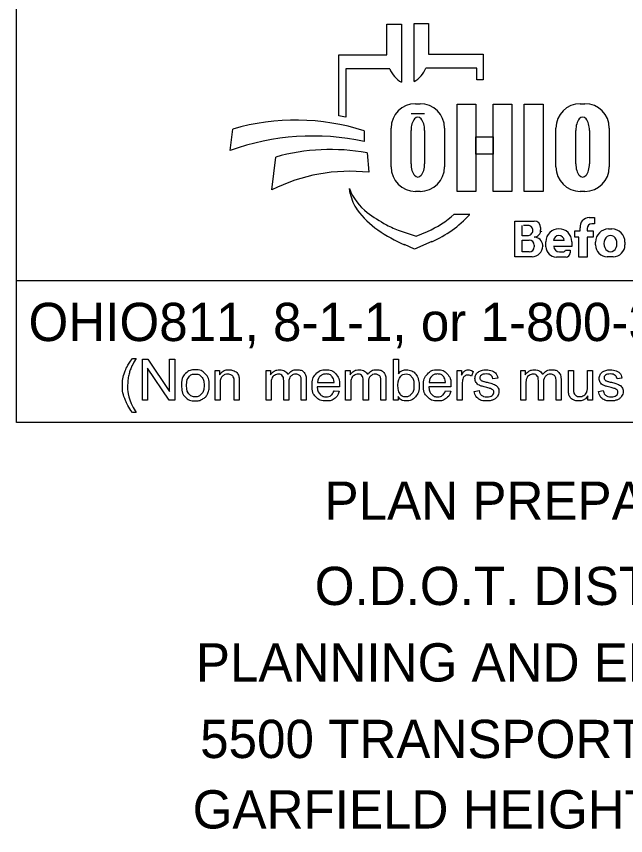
# Model space of a CAD drawing. Extents: x -17.5 to 72.9, y -57.8 to 32.3.
# Drawn here: x 41.886 to 44.116, y -57.698 to -54.7 of the extents above; entities that cross this region are included whole.
import ezdxf

# ---------------------------------------------------------------- set-up
doc = ezdxf.new("R2010")
doc.units = 0
doc.layers.add('SH_Data', color=7, linetype='Continuous')
doc.layers.add('SH_Text', color=7, linetype='Continuous')

msp = doc.modelspace()

# ---------------------------------------------------------------- linework, layer by layer
at = {"layer": 'SH_Data'}
for p, q in [((41.8861, -56.1862), (41.8861, -53.8487)), ((46.1361, -55.6683), (41.8861, -55.6683)), ((46.1361, -56.1862), (41.8861, -56.1862))]:
    msp.add_line(p, q, dxfattribs=at)
at = {"layer": 'SH_Text'}
for p, q in [((43.2421, -54.8407), (43.2421, -54.7292)), ((43.2421, -54.7292), (43.2957, -54.7292)), ((43.2957, -54.7292), (43.2957, -54.9412)), ((43.3414, -54.9389), (43.3414, -54.7268)), ((43.3414, -54.7268), (43.395, -54.7268)), ((43.395, -54.7268), (43.395, -54.8383)), ((43.0661, -55.0646), (43.0661, -54.8407)), ((43.0661, -54.8407), (43.2421, -54.8407)), ((43.395, -54.8383), (43.5943, -54.8383)), ((43.5943, -54.8383), (43.5943, -54.9322)), ((43.571, -54.8898), (43.3846, -54.8898)), ((43.571, -54.9322), (43.571, -54.8898)), ((43.0914, -54.8921), (43.0914, -55.069)), ((43.2525, -54.8921), (43.0914, -54.8921)), ((43.5943, -54.9322), (43.571, -54.9322)), ((43.3471, -55.0198), (43.3636, -55.0198)), ((43.9501, -55.0198), (43.9667, -55.0198)), ((43.3804, -55.0569), (43.3306, -55.0569)), ((42.6688, -55.1909), (42.6782, -55.1127)), ((43.1594, -55.1192), (43.1594, -55.158)), ((43.2576, -55.2513), (43.2576, -55.1093)), ((43.3305, -55.2399), (43.3305, -55.1176)), ((43.3803, -55.1176), (43.3803, -55.2399)), ((43.4531, -55.1093), (43.4531, -55.2513)), ((43.8607, -55.2513), (43.8607, -55.1093)), ((43.9336, -55.2399), (43.9336, -55.1176)), ((43.9834, -55.1176), (43.9834, -55.2399)), ((44.0561, -55.1093), (44.0561, -55.2513)), ((42.8206, -55.3354), (42.8353, -55.2153)), ((43.1694, -55.1998), (43.1756, -55.2708)), ((43.1083, -55.3483), (43.1052, -55.3304)), ((43.3636, -55.3408), (43.3471, -55.3408)), ((43.9667, -55.3408), (43.9501, -55.3408)), ((43.4886, -55.4242), (43.546, -55.4242)), ((43.7099, -55.5799), (43.7099, -55.4492)), ((43.7099, -55.4492), (43.7811, -55.4492)), ((43.9825, -55.4364), (44.0019, -55.4364)), ((44.0019, -55.4599), (43.9918, -55.4599)), ((44.0019, -55.4364), (44.0019, -55.4594)), ((43.2902, -55.4845), (43.3496, -55.505)), ((43.3496, -55.505), (43.3906, -55.4872)), ((43.7378, -55.5027), (43.7378, -55.4657)), ((43.763, -55.4657), (43.7418, -55.4657)), ((43.8048, -55.473), (43.8048, -55.4809)), ((43.9299, -55.5078), (43.9299, -55.4848)), ((43.9299, -55.4848), (43.9492, -55.4848)), ((43.9492, -55.4848), (43.9492, -55.4743)), ((43.9753, -55.4763), (43.9753, -55.4848)), ((43.9753, -55.4848), (43.9968, -55.4848)), ((43.9968, -55.4848), (43.9968, -55.5078)), ((44.0537, -55.4782), (44.0658, -55.4782)), ((43.7573, -55.5027), (43.7378, -55.5027)), ((43.7378, -55.5621), (43.7378, -55.5192)), ((43.7378, -55.5192), (43.7634, -55.5192)), ((43.891, -55.5207), (43.8525, -55.5207)), ((43.9448, -55.5078), (43.9299, -55.5078)), ((43.9448, -55.5811), (43.9448, -55.5078)), ((43.9968, -55.5078), (43.9753, -55.5078)), ((43.9753, -55.5078), (43.9753, -55.5811)), ((43.3436, -55.552), (43.3062, -55.5356)), ((43.4068, -55.5246), (43.3436, -55.552)), ((43.7815, -55.5373), (43.7815, -55.5437)), ((43.8129, -55.5402), (43.8129, -55.5406)), ((43.8244, -55.5431), (43.8244, -55.5247)), ((43.919, -55.5424), (43.8525, -55.5424)), ((43.919, -55.5247), (43.919, -55.5424)), ((44.0059, -55.5368), (44.0059, -55.526)), ((44.1136, -55.526), (44.1136, -55.5368)), ((43.7735, -55.5799), (43.7099, -55.5799)), ((43.7631, -55.5621), (43.7378, -55.5621)), ((43.8735, -55.5616), (43.8876, -55.5616)), ((43.8962, -55.5561), (43.913, -55.5561)), ((43.913, -55.5561), (43.913, -55.5659)), ((44.0708, -55.5796), (44.0486, -55.5796)), ((43.8978, -55.5811), (43.8624, -55.5811)), ((43.9753, -55.5811), (43.9448, -55.5811))]:
    msp.add_line(p, q, dxfattribs=at)
for points in [[(43.4995, -55.0209), (43.5675, -55.0209), (43.5675, -55.3409), (43.4995, -55.3409)], [(43.6317, -55.0209), (43.6996, -55.0209), (43.6996, -55.3409), (43.6317, -55.3409)], [(43.745, -55.0209), (43.8138, -55.0209), (43.8138, -55.3409), (43.745, -55.3409)], [(43.5675, -55.1408), (43.6317, -55.1408), (43.6317, -55.2048), (43.5675, -55.2048)]]:
    msp.add_lwpolyline(points, close=True, dxfattribs=at)
for points in [[(42.3107, -55.9524), (42.3239, -55.9524)], [(42.3474, -56.105), (42.3474, -55.9549), (42.3678, -55.9549), (42.4468, -56.0728), (42.4468, -55.9549), (42.4658, -55.9549), (42.4658, -56.105), (42.4454, -56.105), (42.3664, -55.9871), (42.3664, -56.105), (42.3474, -56.105)], [(43.2829, -56.105), (43.2658, -56.105), (43.2658, -55.9549), (43.2843, -55.9549), (43.2843, -56.0084)], [(42.6134, -56.105), (42.6134, -55.9962), (42.63, -55.9962), (42.63, -56.0117)], [(42.7998, -56.105), (42.7998, -55.9962), (42.8163, -55.9962), (42.8163, -56.0116)], [(43.0912, -56.105), (43.0912, -55.9962), (43.1077, -55.9962), (43.1077, -56.0116)], [(43.499, -56.105), (43.499, -55.9962), (43.5156, -55.9962), (43.5156, -56.0127)], [(43.558, -55.9997), (43.5516, -56.0167)], [(43.7322, -56.105), (43.7322, -55.9962), (43.7487, -55.9962), (43.7487, -56.0116)], [(43.9065, -56.0636), (43.9065, -55.9962), (43.9249, -55.9962), (43.9249, -56.0565)], [(43.9762, -56.0545), (43.9762, -55.9962), (43.9946, -55.9962), (43.9946, -56.105), (43.9781, -56.105)], [(42.9473, -56.0304), (42.9473, -56.105), (42.9289, -56.105), (42.9289, -56.0365)], [(43.2387, -56.0304), (43.2387, -56.105), (43.2203, -56.105), (43.2203, -56.0365)], [(43.648, -56.0244), (43.6299, -56.0268)], [(43.8797, -56.0304), (43.8797, -56.105), (43.8613, -56.105), (43.8613, -56.0365)], [(44.1025, -56.0244), (44.0845, -56.0268)], [(42.6318, -56.0457), (42.6318, -56.105), (42.6134, -56.105)], [(42.7017, -56.0382), (42.7017, -56.105), (42.6833, -56.105), (42.6833, -56.0389)], [(42.8182, -56.0486), (42.8182, -56.105), (42.7998, -56.105)], [(42.8829, -56.0419), (42.8829, -56.105), (42.8645, -56.105), (42.8645, -56.0344)], [(43.0685, -56.0554), (42.9874, -56.0554)], [(42.9884, -56.0403), (43.0492, -56.0403)], [(43.1096, -56.0486), (43.1096, -56.105), (43.0912, -56.105)], [(43.1743, -56.0419), (43.1743, -56.105), (43.1558, -56.105), (43.1558, -56.0344)], [(43.4765, -56.0554), (43.3954, -56.0554)], [(43.3964, -56.0403), (43.4572, -56.0403)], [(43.5174, -56.0481), (43.5174, -56.105), (43.499, -56.105)], [(43.7506, -56.0486), (43.7506, -56.105), (43.7322, -56.105)], [(43.8153, -56.0419), (43.8153, -56.105), (43.7968, -56.105), (43.7968, -56.0344)], [(43.049, -56.0699), (43.068, -56.0723)], [(43.457, -56.0699), (43.476, -56.0723)], [(43.5616, -56.0725), (43.5798, -56.0697)], [(43.9781, -56.105), (43.9781, -56.089)], [(44.0161, -56.0725), (44.0343, -56.0697)], [(43.2829, -56.0914), (43.2829, -56.105)], [(42.3239, -56.1492), (42.3107, -56.1492)]]:
    msp.add_lwpolyline(points, dxfattribs=at)
for centre, radius, start, end in [((43.2933, -54.853), 0.0985, 299.2531, 338.0704), ((43.3438, -54.8553), 0.0985, 201.9296, 240.7469), ((43.3471, -55.1093), 0.0895, 90, 180), ((43.3636, -55.1093), 0.0895, 0, 90), ((43.9501, -55.1093), 0.0895, 90, 180), ((43.9667, -55.1093), 0.0895, 0, 90), ((42.938, -55.8735), 0.8191, 79.2074, 81.0007), ((42.9082, -55.8988), 0.8191, 72.1402, 106.3144), ((42.9713, -56.0299), 0.8919, 77.8238, 109.8274), ((43.0352, -55.9196), 0.7322, 79.44, 105.8467), ((43.1073, -55.9028), 0.6357, 83.8248, 116.8021), ((43.3471, -55.2513), 0.0895, 180, 270), ((43.3636, -55.2513), 0.0895, 270, 0), ((43.9501, -55.2513), 0.0895, 180, 270), ((43.9667, -55.2513), 0.0895, 270, 0), ((43.2926, -55.2583), 0.2008, 201.0457, 232.5314), ((43.2496, -55.3242), 0.1433, 189.6817, 216.0884), ((43.3833, -55.2267), 0.3088, 216.0884, 235.7167), ((43.4852, -55.007), 0.5173, 232.5314, 241.794), ((43.2472, -55.1568), 0.3602, 293.4582, 312.0712), ((43.2472, -55.1568), 0.401, 293.4582, 317.8286), ((43.7811, -55.473), 0.0238, 0, 90), ((43.9825, -55.4699), 0.0335, 90, 187.5187), ((43.9918, -55.4763), 0.0165, 90, 180), ((43.5498, -54.9825), 0.6044, 235.7167, 246.2325), ((43.4, -55.1659), 0.3371, 241.794, 250.9821), ((43.7573, -55.4839), 0.0187, 270, 2.0582), ((43.7591, -55.4826), 0.0169, 357.8325, 90), ((43.7807, -55.4837), 0.0243, 270, 6.6529), ((43.7912, -55.4852), 0.0175, 347.4023, 0), ((43.8717, -55.5247), 0.0473, 0, 180), ((44.0537, -55.526), 0.0478, 90, 180), ((44.0658, -55.526), 0.0478, 0, 90), ((43.7634, -55.5373), 0.0181, 0, 90), ((43.7808, -55.5401), 0.0321, 4.0748, 90), ((43.8717, -55.5217), 0.0193, 2.9632, 177.0368), ((43.7631, -55.5437), 0.0184, 270, 0), ((43.7735, -55.5406), 0.0393, 270, 0), ((43.7799, -55.5402), 0.033, 0, 11.7502), ((43.8624, -55.5431), 0.038, 180, 270), ((43.8735, -55.5406), 0.021, 184.827, 270), ((44.0486, -55.5368), 0.0428, 180, 270), ((44.0708, -55.5368), 0.0428, 270, 0), ((43.8876, -55.5523), 0.00938, 270, 335.9979), ((43.8978, -55.5659), 0.0152, 270, 0)]:
    msp.add_arc(centre, radius, start, end, dxfattribs=at)
for centre, major_axis, ratio, start_param, end_param in [((43.3554, -55.1176), (0, 0.0484), 0.514403, 4.712389, 7.853982), ((43.9585, -55.1176), (0, 0.0484), 0.514403, 4.712389, 7.853982), ((43.3554, -55.2399), (0, 0.0484), 0.514403, 1.570796, 4.712389), ((43.9585, -55.2399), (0, 0.0484), 0.514403, 1.570796, 4.712389), ((44.0602, -55.5314), (0, 0.029), 0.832186, 4.712389, 7.853982), ((44.0602, -55.5314), (0, 0.0302), 0.797287, 1.570796, 4.712389)]:
    msp.add_ellipse(centre, major_axis=major_axis, ratio=ratio, start_param=start_param, end_param=end_param, dxfattribs=at)
for points in [[(42.3107, -56.1492), (42.2954, -56.13), (42.2849, -56.1042), (42.2743, -56.0783), (42.2743, -56.0507), (42.2743, -56.0263), (42.2822, -56.004), (42.2914, -55.9781), (42.3107, -55.9524)], [(42.3239, -55.9524), (42.3115, -55.9737), (42.3075, -55.9828), (42.3013, -55.9969), (42.2977, -56.0123), (42.2933, -56.0314), (42.2933, -56.0508), (42.2933, -56.1001), (42.3239, -56.1492)], [(42.4899, -56.0506), (42.4899, -56.0204), (42.5067, -56.0059), (42.5207, -55.9938), (42.5409, -55.9938), (42.5633, -55.9938), (42.5775, -56.0085), (42.5918, -56.0232), (42.5918, -56.0491), (42.5918, -56.0701), (42.5855, -56.0821), (42.5792, -56.0941), (42.5671, -56.1008), (42.5551, -56.1074), (42.5409, -56.1074), (42.5181, -56.1074), (42.504, -56.0928), (42.4899, -56.0782), (42.4899, -56.0506)], [(42.63, -56.0117), (42.642, -55.9938), (42.6646, -55.9938), (42.6744, -55.9938), (42.6827, -55.9973), (42.6909, -56.0009), (42.695, -56.0066), (42.6991, -56.0123), (42.7007, -56.0202), (42.7017, -56.0253), (42.7017, -56.0382)], [(42.8163, -56.0116), (42.8214, -56.0036), (42.8299, -55.9987), (42.8384, -55.9938), (42.8493, -55.9938), (42.8614, -55.9938), (42.8691, -55.9988), (42.8768, -56.0039), (42.88, -56.0129), (42.8929, -55.9938), (42.9137, -55.9938), (42.9299, -55.9938), (42.9386, -56.0028), (42.9473, -56.0117), (42.9473, -56.0304)], [(43.068, -56.0723), (43.0635, -56.089), (43.0513, -56.0982), (43.0392, -56.1074), (43.0202, -56.1074), (42.9964, -56.1074), (42.9824, -56.0928), (42.9684, -56.0781), (42.9684, -56.0515), (42.9684, -56.0241), (42.9825, -56.009), (42.9967, -55.9938), (43.0192, -55.9938), (43.041, -55.9938), (43.0548, -56.0087), (43.0687, -56.0235), (43.0687, -56.0505), (43.0687, -56.0521), (43.0685, -56.0554)], [(43.1077, -56.0116), (43.1128, -56.0036), (43.1213, -55.9987), (43.1298, -55.9938), (43.1407, -55.9938), (43.1527, -55.9938), (43.1605, -55.9988), (43.1682, -56.0039), (43.1714, -56.0129), (43.1843, -55.9938), (43.205, -55.9938), (43.2213, -55.9938), (43.23, -56.0028), (43.2387, -56.0117), (43.2387, -56.0304)], [(43.2843, -56.0084), (43.2959, -55.9938), (43.3141, -55.9938), (43.3241, -55.9938), (43.3331, -55.9978), (43.342, -56.0019), (43.3478, -56.0092), (43.3536, -56.0165), (43.3569, -56.0269), (43.3601, -56.0372), (43.3601, -56.049), (43.3601, -56.0769), (43.3463, -56.0922), (43.3325, -56.1074), (43.3131, -56.1074), (43.2939, -56.1074), (43.2829, -56.0914)], [(43.476, -56.0723), (43.4715, -56.089), (43.4593, -56.0982), (43.4472, -56.1074), (43.4282, -56.1074), (43.4043, -56.1074), (43.3904, -56.0928), (43.3764, -56.0781), (43.3764, -56.0515), (43.3764, -56.0241), (43.3905, -56.009), (43.4047, -55.9938), (43.4272, -55.9938), (43.449, -55.9938), (43.4628, -56.0087), (43.4766, -56.0235), (43.4766, -56.0505), (43.4766, -56.0521), (43.4765, -56.0554)], [(43.5156, -56.0127), (43.5219, -56.0012), (43.5273, -55.9975), (43.5326, -55.9938), (43.5391, -55.9938), (43.5484, -55.9938), (43.558, -55.9997)], [(43.5798, -56.0697), (43.5813, -56.0806), (43.5883, -56.0865), (43.5954, -56.0923), (43.608, -56.0923), (43.6208, -56.0923), (43.6269, -56.0872), (43.6331, -56.082), (43.6331, -56.075), (43.6331, -56.0687), (43.6276, -56.0652), (43.6238, -56.0627), (43.6088, -56.0589), (43.5885, -56.0538), (43.5806, -56.05), (43.5728, -56.0463), (43.5687, -56.0397), (43.5646, -56.0331), (43.5646, -56.0251), (43.5646, -56.0179), (43.568, -56.0117), (43.5713, -56.0055), (43.5771, -56.0014), (43.5814, -55.9982), (43.5888, -55.996), (43.5963, -55.9938), (43.6048, -55.9938), (43.6176, -55.9938), (43.6273, -55.9975), (43.637, -56.0012), (43.6416, -56.0075), (43.6462, -56.0138), (43.648, -56.0244)], [(43.7487, -56.0116), (43.7538, -56.0036), (43.7623, -55.9987), (43.7708, -55.9938), (43.7817, -55.9938), (43.7937, -55.9938), (43.8015, -55.9988), (43.8092, -56.0039), (43.8124, -56.0129), (43.8253, -55.9938), (43.846, -55.9938), (43.8623, -55.9938), (43.871, -56.0028), (43.8797, -56.0117), (43.8797, -56.0304)], [(44.0343, -56.0697), (44.0359, -56.0806), (44.0429, -56.0865), (44.0499, -56.0923), (44.0626, -56.0923), (44.0753, -56.0923), (44.0815, -56.0872), (44.0877, -56.082), (44.0877, -56.075), (44.0877, -56.0687), (44.0822, -56.0652), (44.0784, -56.0627), (44.0633, -56.0589), (44.043, -56.0538), (44.0352, -56.05), (44.0273, -56.0463), (44.0233, -56.0397), (44.0192, -56.0331), (44.0192, -56.0251), (44.0192, -56.0179), (44.0226, -56.0117), (44.0259, -56.0055), (44.0316, -56.0014), (44.0359, -55.9982), (44.0434, -55.996), (44.0508, -55.9938), (44.0593, -55.9938), (44.0722, -55.9938), (44.0819, -55.9975), (44.0916, -56.0012), (44.0962, -56.0075), (44.1008, -56.0138), (44.1025, -56.0244)], [(42.5089, -56.0506), (42.5089, -56.0715), (42.518, -56.0819), (42.5271, -56.0923), (42.5409, -56.0923), (42.5546, -56.0923), (42.5637, -56.0819), (42.5728, -56.0714), (42.5728, -56.05), (42.5728, -56.0298), (42.5636, -56.0194), (42.5545, -56.009), (42.5409, -56.009), (42.5271, -56.009), (42.518, -56.0194), (42.5089, -56.0297), (42.5089, -56.0506)], [(42.6833, -56.0389), (42.6833, -56.0276), (42.6812, -56.0221), (42.679, -56.0165), (42.6735, -56.0132), (42.6681, -56.0098), (42.6607, -56.0098), (42.6489, -56.0098), (42.6404, -56.0173), (42.6318, -56.0248), (42.6318, -56.0457)], [(42.8645, -56.0344), (42.8645, -56.0221), (42.86, -56.016), (42.8554, -56.0098), (42.8452, -56.0098), (42.8374, -56.0098), (42.8308, -56.0139), (42.8242, -56.018), (42.8212, -56.0259), (42.8182, -56.0338), (42.8182, -56.0486)], [(42.9289, -56.0365), (42.9289, -56.0255), (42.9271, -56.0206), (42.9253, -56.0158), (42.9206, -56.0128), (42.9159, -56.0098), (42.9095, -56.0098), (42.8981, -56.0098), (42.8905, -56.0175), (42.8829, -56.0251), (42.8829, -56.0419)], [(43.0492, -56.0403), (43.048, -56.0265), (43.0422, -56.0196), (43.0334, -56.0089), (43.0194, -56.0089), (43.0067, -56.0089), (42.998, -56.0174), (42.9893, -56.026), (42.9884, -56.0403)], [(43.1558, -56.0344), (43.1558, -56.0221), (43.1513, -56.016), (43.1468, -56.0098), (43.1366, -56.0098), (43.1288, -56.0098), (43.1222, -56.0139), (43.1155, -56.018), (43.1126, -56.0259), (43.1096, -56.0338), (43.1096, -56.0486)], [(43.2203, -56.0365), (43.2203, -56.0255), (43.2185, -56.0206), (43.2167, -56.0158), (43.212, -56.0128), (43.2073, -56.0098), (43.2009, -56.0098), (43.1894, -56.0098), (43.1818, -56.0175), (43.1743, -56.0251), (43.1743, -56.0419)], [(43.2827, -56.0498), (43.2827, -56.0694), (43.288, -56.0781), (43.2967, -56.0923), (43.3115, -56.0923), (43.3236, -56.0923), (43.3323, -56.0818), (43.3411, -56.0713), (43.3411, -56.0505), (43.3411, -56.0292), (43.3327, -56.0191), (43.3243, -56.0089), (43.3123, -56.0089), (43.3002, -56.0089), (43.2915, -56.0194), (43.2827, -56.0299), (43.2827, -56.0498)], [(43.4572, -56.0403), (43.456, -56.0265), (43.4502, -56.0196), (43.4414, -56.0089), (43.4274, -56.0089), (43.4147, -56.0089), (43.406, -56.0174), (43.3973, -56.026), (43.3964, -56.0403)], [(43.5516, -56.0167), (43.5448, -56.0128), (43.5381, -56.0128), (43.5321, -56.0128), (43.5273, -56.0164), (43.5225, -56.0201), (43.5205, -56.0265), (43.5174, -56.0364), (43.5174, -56.0481)], [(43.6299, -56.0268), (43.6287, -56.0183), (43.6228, -56.0136), (43.6169, -56.0089), (43.6061, -56.0089), (43.5934, -56.0089), (43.5879, -56.0131), (43.5825, -56.0173), (43.5825, -56.023), (43.5825, -56.0266), (43.5848, -56.0294), (43.587, -56.0324), (43.5918, -56.0344), (43.5946, -56.0354), (43.6081, -56.0391), (43.6277, -56.0443), (43.6355, -56.0476), (43.6432, -56.0509), (43.6477, -56.0573), (43.6521, -56.0636), (43.6521, -56.0731), (43.6521, -56.0823), (43.6467, -56.0904), (43.6413, -56.0985), (43.6311, -56.103), (43.621, -56.1074), (43.6082, -56.1074), (43.5869, -56.1074), (43.5758, -56.0986), (43.5646, -56.0898), (43.5616, -56.0725)], [(43.7968, -56.0344), (43.7968, -56.0221), (43.7923, -56.016), (43.7878, -56.0098), (43.7776, -56.0098), (43.7698, -56.0098), (43.7632, -56.0139), (43.7565, -56.018), (43.7536, -56.0259), (43.7506, -56.0338), (43.7506, -56.0486)], [(43.8613, -56.0365), (43.8613, -56.0255), (43.8595, -56.0206), (43.8577, -56.0158), (43.853, -56.0128), (43.8483, -56.0098), (43.8419, -56.0098), (43.8304, -56.0098), (43.8228, -56.0175), (43.8153, -56.0251), (43.8153, -56.0419)], [(44.0845, -56.0268), (44.0832, -56.0183), (44.0773, -56.0136), (44.0714, -56.0089), (44.0607, -56.0089), (44.0479, -56.0089), (44.0425, -56.0131), (44.0371, -56.0173), (44.0371, -56.023), (44.0371, -56.0266), (44.0393, -56.0294), (44.0416, -56.0324), (44.0464, -56.0344), (44.0492, -56.0354), (44.0627, -56.0391), (44.0823, -56.0443), (44.0901, -56.0476), (44.0978, -56.0509), (44.1022, -56.0573), (44.1067, -56.0636), (44.1067, -56.0731), (44.1067, -56.0823), (44.1013, -56.0904), (44.0959, -56.0985), (44.0857, -56.103), (44.0756, -56.1074), (44.0627, -56.1074), (44.0415, -56.1074), (44.0303, -56.0986), (44.0192, -56.0898), (44.0161, -56.0725)], [(42.9874, -56.0554), (42.9884, -56.0733), (42.9975, -56.0828), (43.0067, -56.0923), (43.0203, -56.0923), (43.0304, -56.0923), (43.0376, -56.087), (43.0448, -56.0816), (43.049, -56.0699)], [(43.3954, -56.0554), (43.3964, -56.0733), (43.4055, -56.0828), (43.4147, -56.0923), (43.4283, -56.0923), (43.4384, -56.0923), (43.4456, -56.087), (43.4528, -56.0816), (43.457, -56.0699)], [(43.9249, -56.0565), (43.9249, -56.071), (43.926, -56.076), (43.9278, -56.0832), (43.9334, -56.0874), (43.939, -56.0915), (43.9473, -56.0915), (43.9556, -56.0915), (43.9629, -56.0873), (43.9702, -56.083), (43.9732, -56.0757), (43.9762, -56.0684), (43.9762, -56.0545)], [(43.9781, -56.089), (43.9654, -56.1074), (43.9436, -56.1074), (43.934, -56.1074), (43.9257, -56.1038), (43.9173, -56.1001), (43.9133, -56.0945), (43.9093, -56.0889), (43.9076, -56.0808), (43.9065, -56.0754), (43.9065, -56.0636)]]:
    msp.add_open_spline(points, degree=3, dxfattribs=at)

# ---------------------------------------------------------------- texts
for s, p in [('OHIO811, 8-1-1, or 1-800-362-2764', (41.9305, -55.8884)), ('PLAN PREPARED BY:', (43.0139, -56.5423)), ('O.D.O.T. DISTRICT 12', (42.9781, -56.8543)), ('PLANNING AND ENGINEERING', (42.543, -57.1343)), ('5500 TRANSPORTATION BLVD.', (42.5587, -57.4143)), ('GARFIELD HEIGHTS, OH 44125', (42.5312, -57.6721))]:
    msp.add_text(s, height=0.14, dxfattribs=at).set_placement(p)

doc.saveas('drawing.dxf')
